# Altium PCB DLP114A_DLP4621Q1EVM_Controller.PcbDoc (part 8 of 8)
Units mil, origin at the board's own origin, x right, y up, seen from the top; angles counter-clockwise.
Board outline 4803.15 x 2598.43 mil, 14 copper layers (Top Layer, GND 1, SIGNAL 1, GND 2, SIGNAL 2, PWR SPLIT PLANE 1, GND 3, GND 4, PWR SPLIT PLANE 2, SIGNAL 3, GND 5, SIGNAL 4, GND 6, Bottom Layer), stack 91.4 mil thick; 489 components, 394 nets, 1925 pads, 1273 vias.
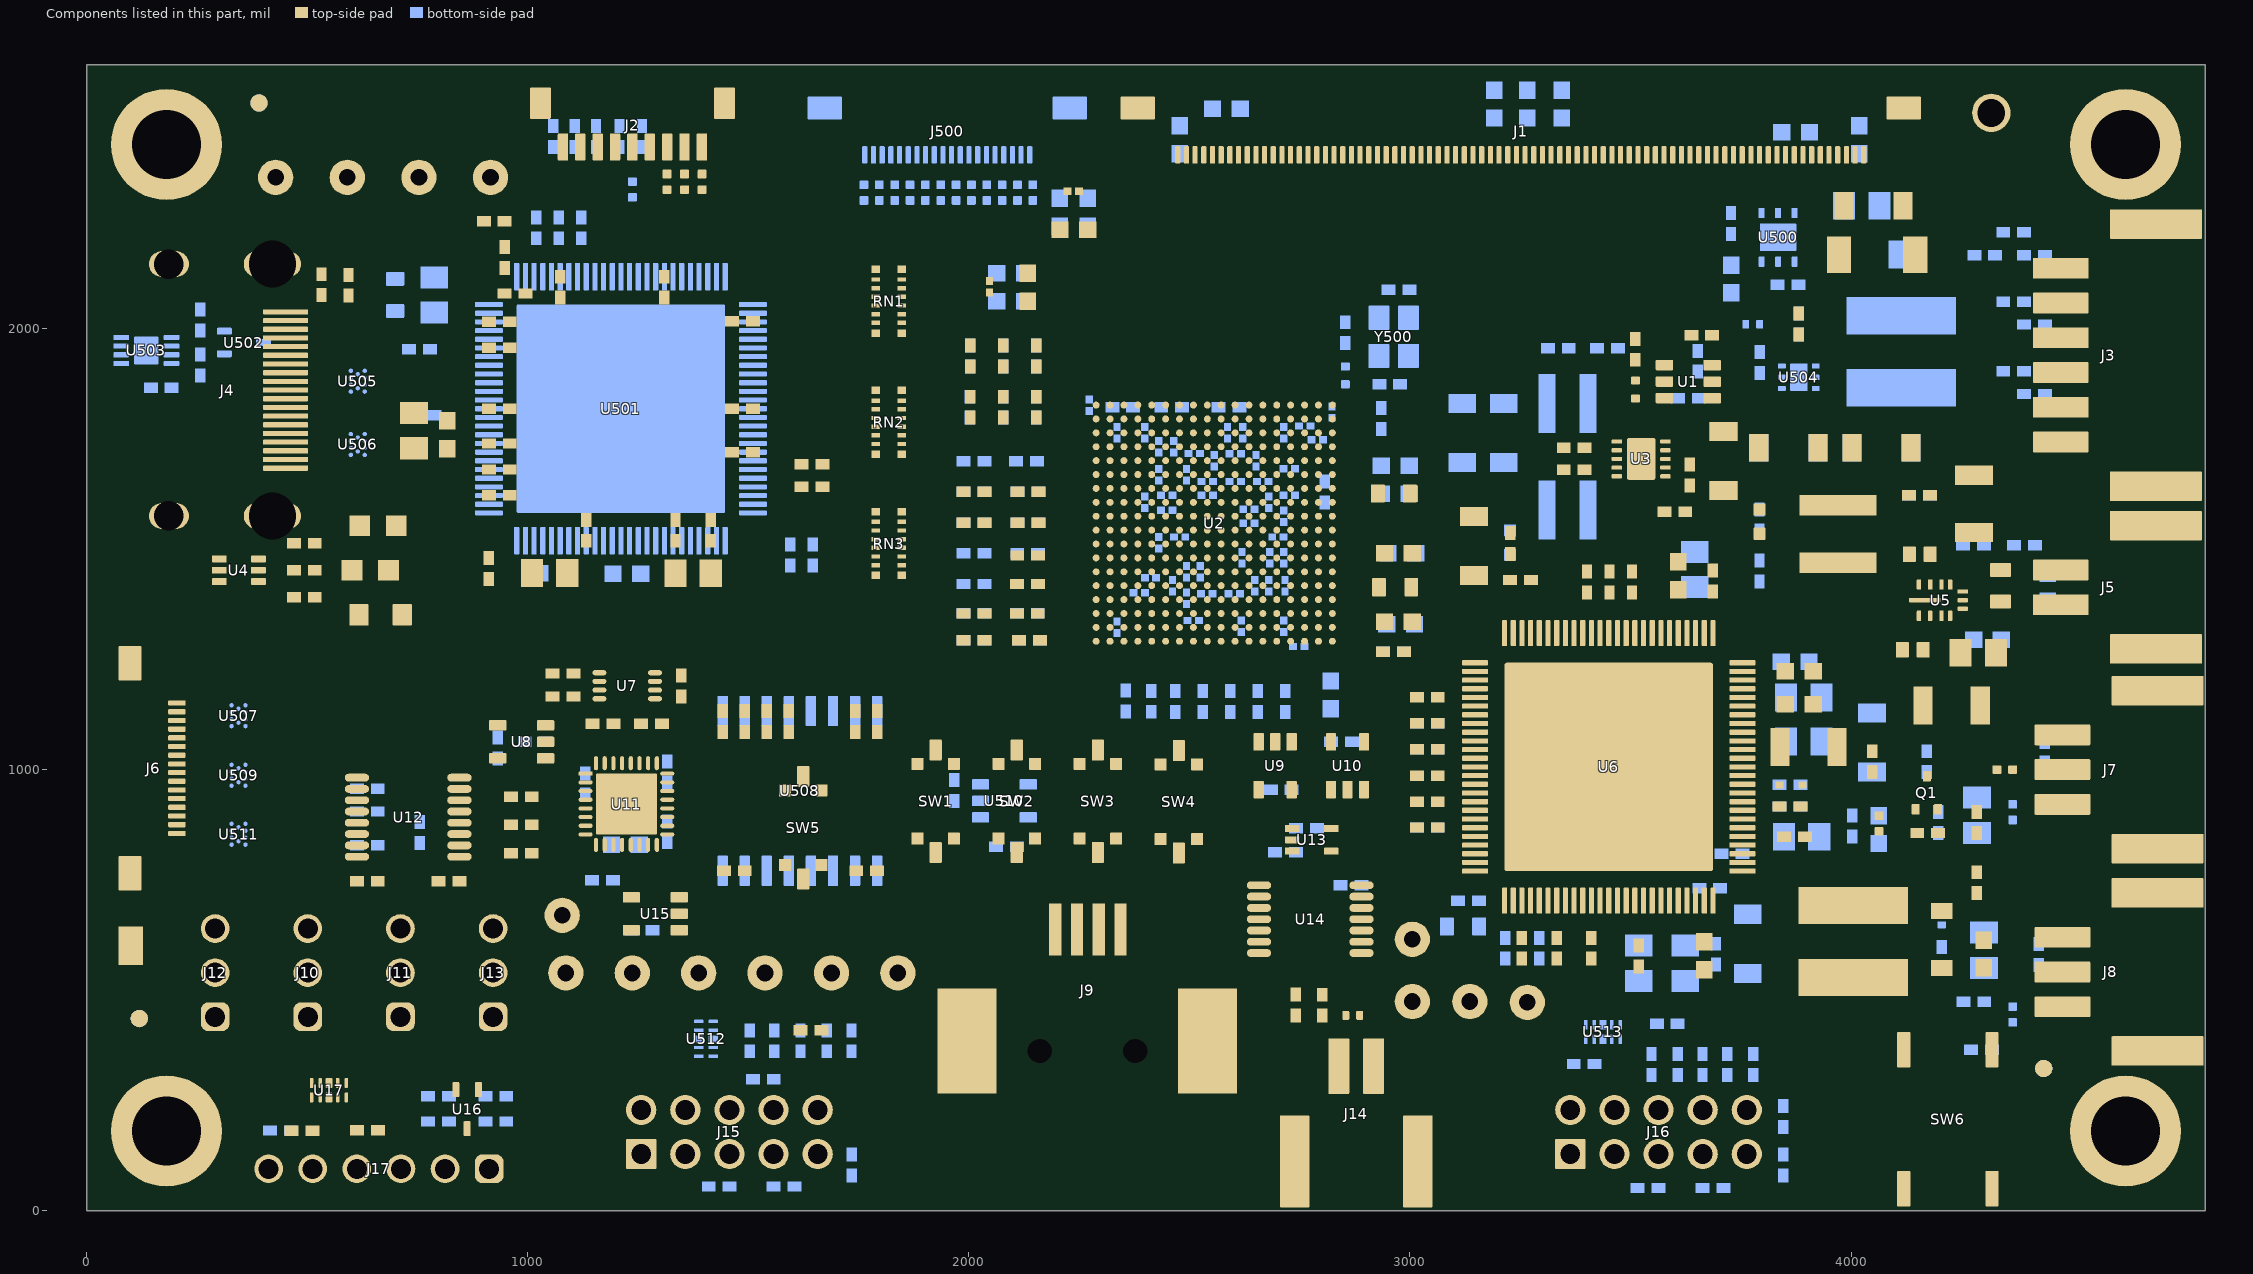
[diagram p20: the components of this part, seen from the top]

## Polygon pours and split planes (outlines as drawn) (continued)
N8V on Bottom Layer "NONET_L-01_P-001" (solid, remove dead copper, pour order 314): 4214.83,1016.03 4260.35,1061.55 4339.43,1061.55 4344.49,1056.5 4344.49,1006.94 4340.09,1002.55 4274.68,1002.55 4236.22,964.09 4184.99,964.09 4163.57,942.67 4013.97,942.67 4009.82,946.83 4009.82,1014.24 4011.61,1016.03
DMD_VRST on Bottom Layer "NONET_L-01_P-001" (solid, remove dead copper, pour order 309): 3244.86,2498.12 3287.33,2498.12 3290.74,2494.71 3290.74,2428.89 3286.34,2424.48 3243.62,2424.48 3239.9,2428.21 3239.9,2496.57 3241.46,2498.14
DMD_VOFS on Bottom Layer "NONET_L-01_P-001" (solid, remove dead copper, pour order 312): 2530.65,2459.41 2530.65,2517.24 2532.86,2519.46 2572.48,2519.46 2574.26,2517.67 2574.26,2430.32 2570.79,2427.3 2570.77,2427.28 2543.45,2427.28 2540.79,2429.94 2540.79,2449.26
DMD_VOFS on Bottom Layer "NONET_L-01_P-001" (solid, remove dead copper, pour order 311): 3323.6,2498.12 3373.61,2498.12 3384.83,2486.9 3384.83,2431.84 3377.47,2424.48 3336.05,2424.48 3318.64,2441.89 3318.64,2496.57 3320.21,2498.14
DMD_VOFS on Bottom Layer "NONET_L-01_P-001" (solid, remove dead copper, pour order 310): 3884.99,2427.07 3884.99,2467.09 3900.29,2482.39 3955.53,2482.39 3961.9,2476.02 3961.9,2433.63 3952.86,2424.59 3887.46,2424.59
DMD_VBIAS on Bottom Layer "NONET_L-01_P-001" (solid, remove dead copper, pour order 308): 3195.36,2498.12 3214.29,2498.12 3225.25,2487.17 3225.25,2430.45 3219.28,2424.48 3178.49,2424.48 3171.65,2431.32 3171.65,2496.51 3173.37,2498.23
P1P8V on Bottom Layer "BOTTOM_LAYER_P1P8V_P207" (solid, pour order 207): 3331.8,1965.29 3331.8,1716.49 3326.37,1711.07 3267.29,1711.07 3261.34,1717.02 3261.34,1766.61 3253.43,1774.52 3092.07,1774.52 3083.79,1782.39 3083.79,1957.65 3095.73,1969.6 3327.49,1969.6
V_DVI_DVDD on Bottom Layer "BOTTOM_LAYER_V_DVI_DVDD_P257" (solid, remove dead copper, pour order 257): 1068.6,1464.8 1068.6,1418.82 1074.85,1412.57 1143.39,1412.57 1148.39,1417.56 1148.39,1465 1141.97,1471.42 1075.22,1471.42
V_DVI_OVDD on Bottom Layer "BOTTOM_LAYER_V_DVI_OVDD_P256" (solid, remove dead copper, pour order 256): 1238.24,1472.71 1339.45,1472.71 1344.59,1467.58 1344.59,1416.59 1338.98,1410.99 1241.35,1410.99 1235.46,1416.87 1235.46,1469.93
V_DVI_PVDD on Bottom Layer "BOTTOM_LAYER_V_DVI_PVDD_P250" (solid, remove dead copper, pour order 250): 670.86,2065.32 826.27,2065.32 831.4,2060.2 831.4,2003.55 825.76,1997.91 755.91,1997.91 746.38,1988.38 672.33,1988.38 666.11,1994.6 666.11,2060.57
P6P5V on Bottom Layer "NONET_L-01_P-001" (solid, remove dead copper, pour order 190): 3875.71,1028.11 3703.11,1028.11 3693.55,1037.68 3693.55,1096.86 3701.83,1105.14 3787.07,1105.14 3817.69,1135.76 3817.69,1192.82 3821.64,1196.77 3878.7,1196.77 3882.02,1193.45 3882.02,1034.43
NetC48_1 on Bottom Layer "NONET_L-01_P-001" (solid, remove dead copper, pour order 183): 3806.65,968.55 3783.26,968.55 3780.36,965.65 3780.36,901.79 3785.39,896.76 3850.69,896.76 3854.75,900.83 3854.75,977.4 3852.33,979.81 3817.92,979.81
VIN_MAIN on Bottom Layer "NONET_L-01_P-001" (solid, remove dead copper, pour order 189): 4148.24,1577.33 4148.24,1517.48 4134.38,1503.62 4134.38,1441.93 4148.24,1428.44 4148.24,1335.77 4109.64,1297.17 4109.64,1081.31 4118.89,1072.06 4217.22,1072.06 4226.35,1081.19 4226.35,1431.99 4201.51,1456.83 4201.51,1473.6 4216.14,1488.23 4262.08,1488.23 4270.41,1496.56 4270.41,1577.15 4262.53,1585.03 4155.94,1585.03
VIN on Bottom Layer "BOTTOM_LAYER_VIN_P188" (solid, pour order 188): 4464.53,1401.69 4329.89,1401.69 4325.37,1397.18 4325.37,1333.12 4330.21,1328.28 4464.74,1328.28 4469.41,1332.96 4469.41,1396.81
P3P3V on Bottom Layer "BOTTOM_LAYER_P3P3V_P222" (solid, remove dead copper, pour order 222): 751.12,2167.83 751.12,2092.76 755.5,2088.38 819.11,2088.38 823.67,2092.93 823.67,2167.85 818.32,2173.2 756.5,2173.2
DVI_5V on Bottom Layer "BOTTOM_LAYER_DVI_5V_P221" (solid, remove dead copper, pour order 221): 172.34,1923.14 172.34,1845.65 180.13,1837.85 266.83,1837.85 272.33,1843.35 272.33,1910.14 267.98,1914.48 236.83,1914.48 224.71,1926.6 175.8,1926.6
GND on Bottom Layer "BOTTOM_LAYER_GND_P220" (solid, remove dead copper, pour order 220): 159.26,1829.96 42.6,1829.96 20.79,1851.77 20.79,1995.36 39.89,2014.46 154.18,2014.46 164.07,2004.57 164.07,1834.77
P6P5V on Bottom Layer "BOTTOM_LAYER_P6P5V_P210" (solid, remove dead copper, pour order 210): 3465.25,628.92 3549.16,628.92 3551.14,626.94 3551.14,575.15 3549.55,573.57 3465.53,573.57 3461.42,577.68 3461.42,625.09
P1P1V on Bottom Layer "BOTTOM_LAYER_P1P1V_P208" (solid, remove dead copper, pour order 208): 3337.5,1658.56 3273.06,1658.56 3245.06,1630.56 3108.77,1630.56 3102.7,1624.5 3102.7,1523.1 3109.02,1516.78 3335.44,1516.78 3341.28,1522.62 3341.28,1654.77
NetL520_1 on Bottom Layer "BOTTOM_LAYER_NETL520_1_P206" (solid, pour order 206): 3383.23,1515.51 3376.17,1522.56 3376.17,1666.45 3382.91,1673.18 3475.23,1673.18 3481.63,1666.79 3481.63,1523.59 3473.55,1515.51
NetL518_1 on Bottom Layer "BOTTOM_LAYER_NETL518_1_P205" (solid, pour order 205): 3380.14,1897.92 3376.17,1893.95 3376.17,1742.54 3382.36,1736.34 3475.77,1736.34 3481.63,1742.2 3481.63,1893.58 3477.28,1897.92
P3P3V on Bottom Layer "NONET_L-01_P-001" (solid, remove dead copper, pour order 186): 3620.57,1799.12 3527.17,1799.12 3523.75,1802.55 3523.75,1849.53 3531.19,1856.97 3621.49,1856.97 3623.36,1855.11 3623.36,1801.91
GND on Bottom Layer "BOTTOM_LAYER_GND_P200" (solid, remove dead copper, pour order 200): 3768.5,1763.14 3812.87,1763.14 3815.15,1760.86 3815.15,1695.71 3812.63,1693.18 3746.96,1693.18 3705.66,1734.48 3652.14,1734.48 3647.06,1739.57 3647.06,1789.36 3652.02,1794.32 3737.32,1794.32
GND on Bottom Layer "BOTTOM_LAYER_GND_P198" (solid, remove dead copper, pour order 198): 4036.96,2323.59 4036.96,2139.63 4045.17,2131.41 4182.59,2131.41 4188.82,2137.65 4188.82,2322.16 4179.16,2331.83 4045.19,2331.83
P6P5V on Bottom Layer "NONET_L-01_P-001" (solid, remove dead copper, pour order 194): 3918.46,2059.86 3918.46,2022.25 3913.1,2016.89 3863.52,2016.89 3859.21,2021.2 3859.21,2158.7 3865.72,2165.21 3886.46,2165.21 3891.71,2170.46 3891.71,2235.48 3879.93,2247.25 3865.21,2247.25 3858.75,2253.72 3858.75,2309.46 3866.8,2317.51 4009.45,2317.51 4016.98,2309.98 4016.98,2107.05 4006.74,2096.13 3954.73,2096.13
P3P3V_REG on Bottom Layer "NONET_L-01_P-001" (solid, remove dead copper, pour order 195): 3638.43,1915.22 3641.72,1918.51 3694.92,1918.51 3699.88,1913.55 3699.88,1869.16 3709.4,1859.63 3781.61,1859.63 3797.43,1843.8 3901.03,1843.8 3911,1853.78 3911,1870.18 3913.37,1872.55 3953.99,1872.55 4004.51,1923.07 4234.68,1923.07 4242.81,1914.93 4242.81,1797.36 4234.91,1789.46 4105.17,1789.46 4074.97,1759.26 4074.97,1596.53 4052.01,1573.57 3679.86,1573.57 3672.28,1581.14 3672.29,1663.65 3680.34,1671.71 3818.5,1671.71 3830.88,1684.09 3830.88,1766.83 3818.25,1779.46 3774.19,1779.46 3744.2,1809.45 3646.55,1809.45 3638.43,1817.57
P1P8V on Bottom Layer "NONET_L-01_P-001" (solid, remove dead copper, pour order 182): 4001.35,2369.61 4059.83,2369.61 4064.84,2374.62 4064.84,2417.43 4059.52,2422.75 4000.95,2422.75 3998.49,2420.44 3998.49,2372.47
NetD1_2 on Bottom Layer "NONET_L-01_P-001" (solid, remove dead copper, pour order 193): 3941.96,1907.78 3914.36,1907.78 3911.49,1910.66 3911.49,1988.57 3934.54,2011.63 3934.54,2052.29 3963.23,2080.99 4030.69,2080.99 4052.06,2102.36 4235.54,2102.36 4245.76,2092.13 4245.76,1982.38 4238.89,1975.51 4009.69,1975.51
NetC26_1 on Bottom Layer "NONET_L-01_P-001" (solid, remove dead copper, pour order 181): 3775.99,1455.89 3804.92,1455.89 3807.57,1458.55 3807.57,1555.56 3804.68,1558.45 3779.16,1558.45 3775.12,1554.42 3775.12,1456.76
NetR500_1 on Bottom Layer "NONET_L-01_P-001" (solid, remove dead copper, pour order 187): 3843.62,2250.7 3843.62,2298.1 3838.99,2302.73 3712.19,2302.73 3708.47,2299 3708.47,2251.28 3714.03,2245.71 3774.73,2245.71 3777.43,2248.4 3841.32,2248.4
P3P3V_TPS99K on Bottom Layer "NONET_L-01_P-001" (solid, remove dead copper, pour order 192): 3637.54,2230.75 3746.59,2230.75 3751,2226.34 3751,2124.05 3747.92,2120.97 3695.97,2120.97 3687.96,2112.96 3687.96,1938.39 3683.44,1933.87 3625.56,1933.87 3622.23,1937.21 3622.23,2215.43
PMIC_ADC_VREF on Bottom Layer "NONET_L-01_P-001" (solid, remove dead copper, pour order 191): 4308.09,1887.98 4359.1,1887.98 4361.23,1890.11 4361.23,2229.77 4359.24,2231.76 4309.14,2231.76 4305.5,2228.12 4305.5,1890.57
P6P5V on PWR SPLIT PLANE 1 "PWR_SPLIT_PLANE_1_P6P5V_P280" (solid, remove dead copper, pour order 280): 1184.59,2238.32 1569.16,2238.32 1635.99,2171.49 2894.19,2171.49 2961.51,2238.81 3095.29,2374.63 3486.95,2374.63 3567.35,2294.23 3567.35,2104.16 3586.41,2085.1 4073.69,2085.1 4139.7,2151.12 4139.7,2460.23 4036.58,2563.35 1198.96,2563.35 1167.18,2531.56 1167.18,2255.74
P3P3V on PWR SPLIT PLANE 1 "PWR_SPLIT_PLANE_1_P3P3V_P283" (solid, remove dead copper, pour order 283): 3499.27,2328.41 3254.09,2328.41 3219.49,2363.01 3109.65,2363.01 2894.99,2148.36 1728.92,2148.36 1678.65,2098.09 1678.65,1587.6 1569.26,1480.72 1430.96,1480.72 1349.56,1399.31 1247.89,1399.31 1171.77,1475.43 878.18,1475.43 786.6,1567.01 786.6,2006.36 1008.59,2228.35 1121.46,2228.35 1147.51,2254.4 1147.51,2546.21 1095.3,2598.43 0,2598.43 0,35.85 2823.11,35.85 3024.59,237.34 3024.05,687.82 3024.05,1105.05 3024.83,1105.83 3024.83,1209.87 3127.98,1313.02 3527.81,1313.02 3633.61,1418.82 3633.61,1862.56 3548.81,1947.36 3548.81,2278.88
VCC18A_LVDS on PWR SPLIT PLANE 1 "PWR_SPLIT_PLANE_1_VCC18A_LVDS_P279" (solid, remove dead copper, pour order 279): 2833.17,1628.58 2833.17,1679.19 2804.02,1709.69 2689.43,1709.69 2657.56,1675.23 2231.79,1675.23 2226.82,1680.2 2226.82,1847.12 2241.53,1860.48 2910.37,1860.48 2937.16,1833.68 2937.16,1627.64 2921.67,1612.14 2849.61,1612.14
P3P3V_TPS99K on PWR SPLIT PLANE 1 "PWR_SPLIT_PLANE_1_P3P3V_TPS99K_P282" (solid, remove dead copper, pour order 282): 3576.68,2070.19 3565.21,2058.71 3565.21,1952.02 3648.27,1868.95 3648.27,1402.67 3542.8,1297.2 3134.26,1297.2 3039.54,1202.48 3039.54,105.64 3112.91,32.27 4193.96,32.27 4328.66,162.87 4328.66,2001.9 4260.37,2070.19
V_DVI_OVDD on PWR SPLIT PLANE 1 "PWR_SPLIT_PLANE_1_V_DVI_OVDD_P281" (solid, remove dead copper, pour order 281): 1423.44,1643.81 1439.51,1665.39 1439.51,2033.6 1426.62,2046.49 1310.47,2046.49 1299.12,2057.85 1299.12,2189.51 1309.12,2198.44 1580.02,2198.44 1648.42,2130.05 1648.42,1585.58 1562.08,1496.27 1430.01,1496.27 1344.73,1410.99 1257.87,1410.99 1178.29,1490.57 885.6,1490.57 834.27,1541.9 834.27,1620.62 857.46,1643.81
P1P8V on PWR SPLIT PLANE 2 "PWR_SPLIT_PLANE_2_P1P8V_P290" (solid, remove dead copper, pour order 290): 3258.18,1301.58 3258.18,1255.07 3260.65,1252.6 3286.81,1252.6 3288.78,1254.57 3288.78,1274.92 3302.86,1289 3578.44,1289 3697.54,1408.1 3697.54,1588.93 3651.23,1635.25 3651.23,1924.11 3695.33,1968.21 4048.78,1968.21 4129.03,2048.46 4129.03,2466.03 4030.32,2564.73 2469.66,2564.73 2380.33,2475.41 2380.33,1704.85 2387.27,1697.92 2798.73,1697.92 2845.17,1651.48 2898.33,1651.48 2936.02,1613.79 3063.83,1613.79 3095.9,1645.85 3296.08,1645.85 3320.93,1621 3320.93,1452.7 3395,1378.63 3395,1342.04 3382.9,1329.93 3286.53,1329.93
P1P1V on PWR SPLIT PLANE 2 "PWR_SPLIT_PLANE_2_P1P1V_P284" (solid, remove dead copper, pour order 284): 2186.35,2210.25 2186.35,2372.76 2195.45,2381.87 2352.13,2381.87 2365.11,2368.89 2365.11,1808.13 2354.24,1797.26 2354.24,1679.13 2361.72,1671.65 2802.53,1671.65 2876.59,1597.59 3069.97,1597.59 3103.19,1630.81 3289.71,1630.81 3304.43,1616.09 3304.43,1467.91 3269.09,1432.57 3269.09,1333.32 3252.51,1317.22 2039.18,1317.22 1977.61,1378.79 1977.61,2180.11 1997.12,2199.65 2175.74,2199.65
P6P5V on PWR SPLIT PLANE 2 "PWR_SPLIT_PLANE_2_P6P5V_P292" (solid, remove dead copper, pour order 292): 1110.26,2054.32 1128.88,2035.7 1128.88,1651.33 1146.73,1633.48 1322.26,1633.48 1333.67,1622.06 1333.67,1590.41 1364.89,1559.2 1364.89,1158.95 1946.83,577 2482.46,577 3616.72,577 3770.33,577 3873.44,680.12 3873.44,1240.62 3832.75,1281.31 3778.42,1281.31 3758.12,1301.61 3614.28,1301.61 3607.59,1294.92 3607.59,1257.14 3576.91,1226.47 3576.91,1210.61 3565.28,1198.98 3230.06,1198.98 3218.12,1210.28 3218.12,1251.48 3176.88,1292.72 3067.54,1292.72 2021.1,1292.72 1957.08,1356.74 1957.08,2220.01 1935.59,2241.5 1754.05,2241.5 1653.55,2342 1158.82,2342 1146.54,2329.72 1146.54,2277.33 1110.26,2241.05
P3P3V_REG on PWR SPLIT PLANE 2 "PWR_SPLIT_PLANE_2_P3P3V_REG_P286" (solid, remove dead copper, pour order 286): 515.32,1577.02 1299.2,1577.02 1333.56,1542.67 1333.56,1155.11 1934.07,554.6 3784.34,554.6 3900.2,670.45 3900.2,1221.29 3963.12,1284.22 4287.7,1284.22 4341.29,1343.02 4341.29,1533.05 4297.32,1577.02 3743.32,1577.02 3681.14,1639.2 3681.14,1912.02 3718.49,1949.38 4709.01,1949.38 4803.15,1855.24 4803.15,0 515.99,0 415.74,100.25 415.74,1477.44
V_DVI_AVDD on PWR SPLIT PLANE 2 "PWR_SPLIT_PLANE_2_V_DVI_AVDD_P285" (solid, remove dead copper, pour order 285): 767.04,1702.67 782.74,1686.97 962.76,1686.97 980.3,1704.51 980.3,1958.27 966.1,1972.47 782.41,1972.47 767.04,1957.09
NetC26_1 on PWR SPLIT PLANE 2 "PWR_SPLIT_PLANE_2_NETC26_1_P291" (solid, remove dead copper, pour order 291): 3796.21,1561.87 3765.98,1531.64 3766.14,1331.76 3795.1,1302.8 4278.13,1302.8 4323.22,1347.89 4323.22,1524.22 4285.57,1561.87
DMD_VRST on SIGNAL 4 "NONET_L-01_P-001" (solid, remove dead copper, pour order 337): 3696.85,769.72 3696.81,635.02 3824.27,507.56 4239.02,507.56 4278.43,546.96 4278.43,722.39 4252.13,748.69 3850.88,748.69 3812.29,787.28 3714.41,787.28
CY_VBUS on SIGNAL 4 "SIGNAL_4_CY_VBUS_P287" (solid, remove dead copper, pour order 287): 2432.18,531.95 2432.18,801.85 2412.33,821.7 2215.82,821.7 2163.62,769.51 2015.23,769.51 1815.58,969.15 1410.64,969.15 1323.66,882.17 1323.66,808.26 1327.44,804.48 1327.44,616.17 1354.15,589.47 1864.54,589.47 1952.97,501.04 2401.27,501.04
N8V_FIL on SIGNAL 4 "NONET_L-01_P-001" (solid, remove dead copper, pour order 322): 4362.05,1031.03 4354.33,1023.31 4354.33,1001.95 4328.81,976.43 4328.81,516.5 4343.55,501.76 4462.61,501.76 4479.11,518.26 4479.11,1020.13 4468.2,1031.03
VIN_MAIN on SIGNAL 4 "SIGNAL_4_VIN_MAIN_P307" (solid, remove dead copper, pour order 307): 3852.33,854.37 3876.82,829.88 4233.08,829.88 4254.79,851.59 4254.79,1125.35 4228.66,1151.48 3872.32,1151.48 3852.33,1131.49
DMD_VBIAS on SIGNAL 1 "NONET_L-01_P-001" (solid, remove dead copper, pour order 333): 3699.97,681.49 3699.97,722.39 3738.28,760.7 3738.28,812.76 3757.93,832.61 3989.87,832.61 4093.68,936.41 4093.68,995.77 3916.97,1172.48 3916.97,1737.63 3356.23,2298.38 3199.21,2298.38 3168.25,2329.34 3168.25,2442.87 3201.26,2475.88 3514.61,2475.88 4142.25,1848.23 4142.25,1229.03 4252.81,1118.48 4252.81,845.37 4077.96,670.52 3710.68,670.79
DMD_VOFS on SIGNAL 1 "NONET_L-01_P-001" (solid, remove dead copper, pour order 332): 3573.44,624.38 3559.94,610.87 3559.94,494.96 3594.41,460.48 4210.76,460.48 4477.52,727.25 4477.52,2220.9 4200,2498.42 3954.34,2498.42 3935.97,2480.05 3935.97,2330.77 4295.53,1971.22 4295.53,823.42 4096.49,624.38
N8V on SIGNAL 1 "NONET_L-01_P-001" (solid, remove dead copper, pour order 326): 3717.76,1026.54 3698.96,1026.54 3694.86,1022.43 3694.86,990.66 3699.57,985.95 3765.76,985.95 3800.2,1020.4 3923.62,1020.4 4010.68,933.33 4052.15,933.33 4061.6,942.78 4061.6,982.68 4054.29,989.99 4036.63,989.99 3946.86,1079.76 3770.98,1079.76
P1P8V on SIGNAL 1 "NONET_L-01_P-001" (solid, remove dead copper, pour order 323): 3079.48,1837.7 3079.48,1690.27 3023.83,1634.61 3023.83,1596.67 3079.48,1541.02 3079.48,1309.98 3100,1289.47 3246.88,1289.47 3258.56,1277.78 3258.56,1249.3 3261.28,1246.58 3285.44,1246.58 3288.42,1249.55 3288.42,1279.64 3298.25,1289.47 3663.41,1289.47 3697.55,1323.6 3697.55,1843.41 3665.68,1875.28 3117.06,1875.28
GND on GND 1 "GND_1_GND_P216" (solid, remove dead copper, pour order 216): 0,2598.43 0,0 4803.15,0 4803.15,2598.43
GND on GND 6 "GND_6_GND_P247" (solid, remove dead copper, pour order 247): 0,2598.43 0,0 4803.15,0 4803.15,2598.43
GND on GND 5 "GND_5_GND_P261" (solid, remove dead copper, pour order 261): 0,2598.43 0,0 4803.15,0 4803.15,2598.43
GND on GND 2 "GND_2_GND_P262" (solid, remove dead copper, pour order 262): 0,2598.43 0,0 4803.15,0 4803.15,2598.43
GND on GND 3 "GND_3_GND_P324" (solid, remove dead copper, pour order 324): 0,2598.43 0,0 4803.15,0 4803.15,2598.43
GND on GND 4 "GND_4_GND_P325" (solid, remove dead copper, pour order 325): 0,2598.43 0,0 4803.15,0 4803.15,2598.43

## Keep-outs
Keep-Out Layer:
  the board outline again, w50
  text ".Layer_Name" at 577,-858.49 h60

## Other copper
Top Layer:
  region net DMD_VOFS: 3673.18,733.32 3662.48,733.39 3660.6,731.52 3660.6,649.42 3637.26,626.07 3575.87,626.07 3564.71,614.91 3564.71,582.47 3572.57,574.61 3612.7,574.61 3627.24,589.15 3686.65,589.15 3689.45,591.95 3689.45,640.44 3673.76,656.13 3673.76,732.74
  region net DMD_VOFS: 2557.83,2373.45 2546.89,2373.34 2544.66,2375.57 2544.66,2430.24 2541.49,2433.41 2541.49,2475.14 2545.84,2479.49 2558.3,2479.49 2563.47,2474.32 2563.47,2432.94 2559.47,2428.94 2559.47,2375.09
  region net DMD_VOFS: 3293.74,2375.46 3293.75,2417.37 3326.77,2450.39 3380.26,2450.39 3384.9,2445.75 3384.9,2433.2 3379.03,2427.33 3319.11,2427.33 3306.44,2414.65 3306.44,2375 3304.98,2373.54 3294.92,2373.54 3293.74,2374.72
  region net DMD_VRST: 3279.28,2447.85 3284.76,2447.85 3290.37,2442.24 3290.37,2425.98 3287.04,2422.81 3287.04,2374.99 3285.73,2373.68 3275.27,2373.68 3274.06,2374.89 3274.06,2376.63 3274.06,2416.47 3265.14,2425.39 3245.27,2425.39 3238.72,2431.94 3238.72,2440.86 3245.75,2447.89 3279.24,2447.89
  region net DMD_VBIAS: 3215,2416.47 3206.09,2425.39 3181.18,2425.39 3174.85,2431.71 3174.85,2441.08 3181.66,2447.89 3220.19,2447.89 3227.99,2440.08 3227.99,2374.99 3226.68,2373.68 3216.21,2373.68 3215,2374.89 3215,2376.63
  region net DMD_VOFS: 3938.83,2476.88 3944.75,2482.8 3956.88,2482.8 3961.57,2478.1 3961.57,2431.13 3956.32,2425.74 3956.02,2374.68 3955.02,2373.68 3944.56,2373.68 3943.35,2374.89 3943.35,2376.63 3943.35,2425.69 3938.83,2430.2
  text ".Layer_Name" at 577,-858.49 h60
Bottom Layer:
  text ".Layer_Name" at 577,-858.49 h60

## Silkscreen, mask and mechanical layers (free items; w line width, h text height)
Top Overlay:
  circle w10: c222.02,1168.9 r0.77
  circle w10: c2375.79,686.59 r5.17
  circle w10: c2799.86,384.08 r4.38
  circle w10: c3594.49,1652.46 r0.39
  circle w10: c269.73,1480.89 r0.39
  circle w10: c4139.27,1324.86 r0.39
  circle w10: c3114.67,1264.52 r0.39
  circle w10: c1303.9,1145.61 r0.39
  circle w10: c1076.29,1022.62 r0.39
  circle w10: c2740.28,1097.24 r0.39
  circle w10: c2803.84,926.7 r0.39
  circle w10: c884.16,797.12 r0.39
  circle w10: c2704.49,884.11 r0.39
  circle w10: c2619.45,748.81 r0.39
  circle w10: c1370.35,616.45 r0.39
  circle w10: c503.49,233.22 r0.39
  lines w6: 802.46,1197.2 819.66,1180 819.66,1066.29 926.15,959.79 ; 850.89,1976.38 877.77,1976.38 ; 866.77,2020.83 878.53,2020.83 ; 887.63,1846.92 887.56,1846.92 887.56,1902.62 897.32,1912.38 ; 999.24,1686.3 1021.84,1686.3 1032.84,1675.3 1032.84,1612.47 ; 1002.18,1153.57 1025.67,1130.09 1085.96,1130.09 1103.92,1112.12 ; 1012.41,1196.74 1022.13,1187.03 ; 1027.95,2075.19 1033.35,2080.58 1033.35,2104.54 ; 1180.73,588.26 1195.77,588.26 1205.3,578.73 ; 1376.81,455.29 1385.49,463.97 1385.49,485.75 ; 2094.93,1261 2094.93,1143.26 2121.23,1116.96 ; 2198.59,1569.1 2205.2,1575.71 2205.2,1686.91 ; 2238.17,1921.52 2355.79,1921.52 2379.3,1945.04 ; 2937.43,1669.38 2937.43,1887.51 2972.66,1922.74 2998.57,1922.74 ; 3072.53,1194.65 3072.53,1647.08 3125.66,1700.21 3125.66,1947.71 3147.2,1969.25 ; 3148.01,411.55 3163.64,411.55 3203.65,451.56 3220.66,451.56 ; 3733.28,1798.61 3748.72,1814.05 ; 4182.46,1659.79 4182.46,1677.34 4197.08,1691.96
  lines w6.1: 517.51,1260.34 534.74,1277.57 534.74,1356.83 ; 2184.2,1971.25 2258.95,2045.99 2315.01,2045.99 2325.6,2056.58 ; 2186.2,1869.55 2238.17,1921.52 ; 3831.1,1263.53 3831.1,1321.79 3840.06,1330.75 ; 4000.96,1078.95 4009.07,1087.06 4009.07,1112.32
  text "HL Driver I/F" at 1473.96,2410.62 h30
  text "PCLK" at 929.89,2404.44 h30 r90
  text "DATAEN" at 806.59,2401.58 h30 r90
  text "DMD I/F" at 2149.66,2394.15 h30
  text "DLP4620SQ1EVM / DLP4621Q1EVM" at 1478.6,2308.87 h30
  text "LED Therm" at 4228.76,2270.15 h30
  text "HSYNC" at 350.71,2258.61 h30
  text "VSYNC" at 528.21,2258.61 h30
  text "DLP090 / DLP092" at 1645.38,2244.5 h30
  text "HDMI" at 225.97,2175.39 h30
  text "Input Power" at 4408.42,1470.54 h45 r90
  text "OpenLDI" at 12.97,1312.95 h30
  text "PhotoDiode1" at 4402.85,1028.29 h45 r90
  text "USB" at 2293.87,669.64 h30
  text "DMUX0" at 2938.22,669.83 h30
  text "AMUX1" at 3170.91,528.1 h30 r90
  text "TESTPT3" at 1931.32,524.05 h30 r90
  text "TESTPT0" at 1172.97,496.75 h30 r90
  text "TESTPT1" at 1627.48,481.07 h30 r90
  text "TESTPT2" at 1783.39,481.07 h30 r90
  text "HOST_SPI_MODE" at 987.84,440.97 h30
  text "DMUX1" at 2960.55,391.95 h30
  text "PMIC SPI" at 3540.87,376.78 h30
  text "Host SPI" at 1317.95,370.53 h30
  text "PhotoDiode2" at 4396.61,371.07 h30 r90
  text "Host SPI CLK" at 430.5,362.29 h30 r90
  text "Host SPI CSZ" at 223.09,360.25 h30 r90
  text "Host SPI POCI" at 854.69,345.45 h30 r90
  text "Host SPI PICO" at 636.57,332.93 h30 r90
  text "AMUX0" at 3137.41,284.2 h30 r90
  text "Proj_ON" at 4422.19,35.94 h30 r90
  text "Host I2C" at 1022.48,9.97 h30 r90
  text "FAN PWM" at 2689.63,-142.49 h30 r90
  text ".Layer_Name" at 577,-858.49 h30
Bottom Overlay:
  drawing of 174 lines, arcs and shapes, not listed
  text "TP2" at 632.46,2403.82 h30
  text "DATAEN" at 736.06,2403.11 h30 r270
  text "TP1" at 460.72,2402.39 h30
  text "HUD Driver I/F" at 1570.79,2333.16 h45 r270
  text "TP4" at 826.71,2305.22 h30 r270
  text "A" at 3520.71,2299.7 h30
  text "HSYNC" at 490.67,2258.61 h30
  text "VSYNC" at 666.25,2257.99 h30
  text "TP3" at 797.76,2254.26 h30
  text "PCLK" at 964.17,2253.89 h30
  text "A" at 2724.07,1820.46 h30
  text "B" at 2424.18,1268.45 h30
  text "TP5" at 993.69,631.34 h30 r270
  text "TP10" at 1590.84,595.02 h30
  text "TP12" at 1886.34,593.82 h30
  text "TP11" at 1734.99,592.62 h30
  text "TP6" at 3052.53,534.31 h30
  text "TP8" at 1293.43,499.51 h30 r270
  text "TP9" at 1440.08,499.7 h30 r270
  text "TP7" at 1123.83,455.32 h30
  text "TP13" at 3048.07,388.05 h30
  text "TP14" at 3189.69,388.05 h30
  text "TP15" at 3321.76,388.05 h30
  text "B" at 2176.99,65.9 h30
  text ".Layer_Name" at 577,-858.49 h60
Top Paste:
  text ".Layer_Name" at 577,-858.49 h60
Bottom Paste:
  text ".Layer_Name" at 577,-858.49 h60
Top Solder:
  text ".Layer_Name" at 577,-858.49 h60
  text ".Layer_Name" at 577,-858.49 h60
Bottom Solder:
  text ".Layer_Name" at 577,-858.49 h60
Drill Guide:
  text ".Layer_Name" at 577,-858.49 h60
M1 Board Outline:
  the board outline again, w10
  text ".Layer_Name" at 577,-858.49 h60
M2 Board Dimensions:
  rectangle: 4953.53,92.93 5078.53,217.93
  rectangle: 5078.53,-32.07 5453.53,92.93
  lines w7: 4953.53,92.93 5953.53,92.93 ; 5078.53,-32.07 5078.53,217.93 ; 5203.53,-32.07 5203.53,217.93 ; 5453.53,-32.07 5453.53,217.93 ; 5703.53,-32.07 5703.53,217.93 ; 4953.53,-32.07 5953.53,-32.07 5953.53,217.93 4953.53,217.93 4953.53,-32.07
  text ".Layer_Name" at 577,-858.49 h60
M3 3D STEP Top:
  text ".Layer_Name" at 577,-858.49 h60
M4 3D STEP Bottom:
  text ".Layer_Name" at 577,-858.49 h60
M5 Assembly Top:
  lines w10: -292,-930.17 6308,-930.17 ; -292,-726.83 6310,-726.83 ; -292,-523.5 -292,-1133.5 3713,-1133.5 6310,-1133.5 6310,-523.5 -291.5,-523.5 -291.5,-1133.5 1284,-1133.5 ; 2173,-1133.5 2173,-523.5 ; 3440,-726.83 3440,-523.5 ; 4280,-726.83 4280,-523.5 ; 4902,-1140 4902,-937.17
  text "COMPONENTS MARKED 'DNP' SHOULD NOT BE POPULATED." at 1153.5,-318.5 h60
  text "ASSEMBLY VARIANT:" at 1153,-434 h60
  text ".VariantName" at 2189,-434 h60
  text "PCB VIEWED FROM TOP SIDE" at -228.5,-655.67 h60
  text "BOARD #:" at 2248,-655.67 h60
  text ".PRJ_Number" at 2793.5,-655.67 h60
  text "REV:" at 3638,-655.67 h60
  text ".PCB_Rev" at 3929.5,-655.67 h60
  text "SVN REV:" at 4476,-655.67 h60
  text ".VersionControl_RevNumber" at 4982,-655.67 h60
  text "TID #:" at 2248,-859 h60
  text ".TID" at 2793.5,-859 h60
  text "PLOT NAME =" at -228.5,-1064.34 h60
  text ".plot_File_Name" at 577,-1064.34 h60
  text "GENERATED    :" at 2250,-1064.34 h60
  text ".Print_Date" at 3119.5,-1064.34 h60
  text ".Print_Time" at 3848.5,-1064.34 h60
  text "TEXAS INSTRUMENTS" at 5113,-1064.34 h60
M6 Assembly Bottom:
  lines w10: -292.5,-727.33 6309.5,-727.33 ; -290.5,-930.67 6309.5,-930.67 ; 1115.5,-1140.5 1115.5,-937.67 ; 1737.5,-727.33 1737.5,-524 ; 2577.5,-727.33 2577.5,-524 ; 3844.5,-1134 3844.5,-524 ; 4733.5,-1134 6309,-1134 6309,-524 -292.5,-524 -292.5,-1134 2304.5,-1134 6309.5,-1134 6309.5,-524
  text "COMPONENTS MARKED 'DNP' SHOULD NOT BE POPULATED." at 6102,-318 h60
  text ".VariantName" at 5058,-434 h60
  text "ASSEMBLY VARIANT:" at 6097,-434 h60
  text ".VersionControl_RevNumber" at 1035.5,-656.17 h60
  text "SVN REV:" at 1541.5,-656.17 h60
  text ".PCB_Rev" at 2088,-656.17 h60
  text "REV:" at 2379.5,-656.17 h60
  text ".PRJ_Number" at 3224,-656.17 h60
  text "BOARD #:" at 3769.5,-656.17 h60
  text "PCB VIEWED FROM BOTTOM SIDE" at 6246,-656.17 h60
  text ".TID" at 3224,-859.5 h60
  text "TID #:" at 3769.5,-859.5 h60
  text "TEXAS INSTRUMENTS" at 904.5,-1064.84 h60
  text ".Print_Time" at 2169,-1064.84 h60
  text ".Print_Date" at 2898,-1064.84 h60
  text "GENERATED    :" at 3767.5,-1064.84 h60
  text ".plot_File_Name" at 5440.5,-1064.84 h60
  text "PLOT NAME =" at 6246,-1064.84 h60
M9 Title Sheet:
  drawing of 61 lines, arcs and shapes, not listed
  text "1" at 739.84,12536.5 h70
  text "2" at 3235.5,12536.5 h70
  text "3" at 5724.84,12536.5 h70
  text "4" at 8231.51,12536.5 h70
  text "5" at 10730.5,12536.5 h70
  text "6" at 13235.5,12536.5 h70
  text "A" at 14373.71,9525.4 h70
  text "A" at -430.84,9478.52 h70
  text "B" at -416.5,6893.5 h70
  text "B" at 14383.5,6893.5 h70
  text "C" at -416.5,4513.5 h70
  text "C" at 14383.5,4513.5 h70
  text "D" at -416.5,2138.5 h70
  text "D" at 14383.5,2138.5 h70
  text "PROJECT TITLE:" at 11343.5,277.5 h45
  text ".PRJ_Title" at 11393.5,144.17 h70
  text "DESIGNED FOR:" at 11343.5,-23.5 h45
  text ".PRJ_Customer" at 11393.5,-163.5 h70
  text "E" at -416.5,-231.5 h70
  text "E" at 14383.5,-231.5 h70
  text "FILE NAME:" at 11343.5,-323.5 h45
  text ".PCB_File_Name_No_Path" at 11393.5,-443.5 h70
  text "Texas Instruments (TI) and/or its licensors do not warrant the accuracy or completeness of this specification" at 6374,-605.34 h45
  text "ENGINEER:" at 11343.5,-613.5 h45
  text "LAYOUT BY:" at 12848.5,-613.5 h45
  text "or any information contained therein. TI and/or its licensors do not warrant that this design will meet" at 6329.01,-718 h45
  text ".PRJ_Engineer" at 11393.5,-768.49 h70
  text ".PCB_Layout" at 12899,-768.49 h70
  text "the specifications, will be suitable for your application or fit for any particular purpose, or will operate in" at 6329.01,-830.67 h45
  text ".Layer_Name" at 577,-858.49 h60
  text "ALTIUM DESIGNER VERSION:" at 12848.5,-923.5 h45
  text "an implementation. TI and/or its licensors do not warrant that the design is production worthy. You should" at 6329.01,-943.33 h45
  text "completely validate and test your design implementation to confirm the system functionality for your application." at 6374,-1056 h45
  text ".print_Scale" at 11393.5,-1056.83 h70
  text ".Application_BuildNumber" at 12899,-1056.83 h70
  text "1" at 739.84,-1263.5 h70
  text "2" at 3235.5,-1263.5 h70
  text "3" at 5724.84,-1263.5 h70
  text "4" at 8231.51,-1263.5 h70
  text "5" at 10730.5,-1263.5 h70
  text "6" at 13235.5,-1263.5 h70
M10 Fab Notes:
  drawing of 219 lines, arcs and shapes, not listed
  text "FAB NOTES :" at -22.41,12208.04 h80
  text "1.  BOARD DIMENSION : 122MM X 66MM." at 141.85,11900.97 h80
  text "2. VENDOR MAY ADJUST SOLDERMASK WHEREVER SOLDERMASK PADS ARE THE SAME SIZE (1:1) AS PER THE MANUFACTURING CAPABILITIES AND" at 138.88,11716.65 h80
  text "ALL OTHER SOLDER MASK PADS SHALL NOT BE MODIFIED, PROVIDED NO ADJACENT COPPER IS EXPOSED AND NO CONFLICT IS PRODUCED WITH ANY STATED \"VIA TENTING/COVERING\" REQUIREMENTS." at 367.79,11541.16 h80
  text "3. ALL VIAS ARE TENTED ON BOTH SIDES UNLESS OTHERWISE SOLDER MASK IS OPENED IN GERBER." at 138.88,11383.7 h80
  text "4. TRACES WITH 6.3MIL TO BE 50 OHMS +/-10% SINGLE ENDED ON TOP LAYER & BOTTOM LAYER (L1 & L14)." at 138.35,11178.73 h80
  text "5. TRACES WITH 4.5MIL TO BE 50 OHMS +/-10% SINGLE ENDED ON SIGNAL1, SIGNAL2, SIGNAL3 & SIGNAL4 LAYERS (L3, L5, L10 & L12)." at 123.35,10938.78 h80
  text "6. TRACES WITH 7MIL AND 14MIL SEPERATION TO BE 90 OHMS +/-10% DIFFERENTIAL ON EXTERNAL LAYER(L1)." at 138.35,10770.27 h80
  text "7. TRACES WITH 5MIL AND 9MIL SEPERATION TO BE 90 OHMS +/-10% DIFFERENTIAL ON INTERNAL LAYER(L3)." at 138.35,10558.64 h80
  text "8. TRACES WITH 5.4MIL AND 11.4MIL SEPERATION TO BE 100 OHMS +/-10% DIFFERENTIAL ON EXTERNAL LAYERS(L1 & L14)." at 138.35,10340.14 h80
  text "9. TRACES WITH 4MIL AND 10MIL SEPERATION TO BE 100 OHMS +/-10% DIFFERENTIAL ON INTERNAL LAYERS(L3 & L12)." at 137.04,10146.36 h80
  text "10. 8.01MIL VIAS NEED TO BE FILLED WITH NON-CONDUCTIVE EPOXY-RESIN AND OVERPLATE WITH COPPER. SURFACE MUST BE FLAT," at 106.28,9936.63 h80
  text "FLATNESS TOLERANCE IS +0.000/-0.001\" ON BOTTOM SIDE ONLY AND +0.000/-0.003\" ON TOP SIDE." at 404,9749.47 h80
  text "MINIMUM ANNULAR RING REQUIREMENT IS WAIVED FOR FILLED VIAS." at 401.75,9567.78 h80
  text "DESIGN INFORMATION" at 12382.02,6356.17 h60
  text "MIN. TRACK WIDTH:" at 11737.46,6224.05 h60
  text "8" at 12833.7,6224.05 h60
  text "MIL" at 12988.46,6224.05 h60
  text "5" at 12833.93,6106.21 h60
  text "MIN. CLEARANCE:" at 11737.46,6099.92 h60
  text "MIL" at 12988.46,6099.92 h60
  text "MIN. VIA PAD SIZE:" at 11737.46,5975.8 h60
  text "24" at 12803.71,5975.8 h60
  text "MIL" at 12988.46,5975.8 h60
  text "0.05mm (2MIL)" at 12432.46,5845.9 h60
  text "MINIMUM ANNULAR RING" at 11408.23,5837.67 h60
  text "EXTERNAL" at 13140.46,5837.67 h60
  text "PER" at 11608.23,5727.55 h60
  text "IPC-D-275 CLASS 2 LEVEL C" at 11828.23,5727.54 h60
  text "MIL, HOLES" at 13316.46,5627.07 h60
  text "+/-" at 12924,5618.48 h60
  text "+/-" at 13778,5618.48 h60
  text "REGISTRATION TOLERANCES:" at 11408.23,5617.42 h60
  text "METAL" at 12608,5617.42 h60
  text "5" at 13184.2,5617.42 h60
  text "3" at 14017.2,5617.42 h60
  text "MIL" at 14133.46,5617.42 h60
  text "HOLE SIZE TOLERANCE (UNLESS OTHERWISE SPECIFIED):" at 11408.23,5519.1 h60
  text "+/-" at 13778,5516.23 h60
  text "3" at 14017.2,5515.17 h60
  text "MIL" at 14133.46,5515.17 h60
  text "MATERIAL:" at 11333.46,5377.52 h60
  text "FR-4 High Tg" at 12319.9,5249 h60
  text "X" at 12175.46,5241.01 h60
  text "FR-408" at 11754.46,5236.49 h60
  text "OTHER" at 13242.46,5236.49 h60
  text "93 MIL +/-10%" at 13653.85,5093.52 h55
  text "62 MIL (1.6mm) +/-10%" at 12074.56,5093.46 h60
  text "X" at 13241.26,5091.77 h60
  text "THICKNESS:" at 11408.23,5085.24 h60
  text "OTHER" at 13359.46,5085.24 h60
  text "TOLERANCE:" at 11408.23,4946.92 h60
  text "X" at 12256.46,4946.92 h60
  text "ANSI IPC-6012 TYPE 3 CLASS 2" at 12434.48,4946.92 h60
  text "OTHER +/-" at 12434.46,4802.73 h60
  text "BOW & TWIST:" at 11408.23,4657.54 h60
  text "X" at 12256.46,4657.54 h60
  text "ANSI IPC-6012 TYPE 3 CLASS 2" at 12434.48,4657.54 h60
  text "OTHER +/-" at 12434.46,4510.85 h60
  text "DRILLING:" at 11333.46,4380.23 h60
  text "NC_DRILL FILES" at 13094.46,4275.04 h60
  text "REFERENCE:" at 11408.23,4271.1 h60
  text "X" at 12065.46,4271.01 h60
  text "AS SHOWN" at 12243.46,4271.1 h60
  text "X" at 12966.46,4271.1 h60
  text "OTHER" at 13392.46,4128.85 h60
  text "PTH COPPER THICKNESS:" at 11407.91,4125.32 h60
  text "X" at 12547.14,4125.32 h60
  text "20-30 um" at 12675.14,4125.32 h60
  text "BOARD FINISH:" at 11333.46,3977.73 h60
  text "SILKSCREEN:" at 11488.68,3867.6 h60
  text "X" at 12446.46,3867.6 h60
  text "TOP" at 12563.46,3867.6 h60
  text "X" at 12956.46,3867.6 h60
  text "BOTTOM" at 13074.46,3867.6 h60
  text "SILKSCREEN COLOR:" at 11488.68,3712.41 h60
  text "X" at 12445.46,3712.41 h60
  text "WHITE" at 12563.46,3712.41 h60
  text "OTHER" at 13074.46,3712.41 h60
  text "X" at 13164.32,3574.6 h60
  text "BLUE" at 13784.43,3573.82 h60
  text "GREEN" at 12694.46,3568.96 h60
  text "OTHER" at 13312.46,3568.96 h60
  text "SOLDER RESIST COLOR:" at 11488.68,3562.1 h60
  text "X" at 13166.9,3417.31 h60
  text "MATTE" at 12694.46,3414.71 h60
  text "SEMI-GLOSS" at 13312,3414.07 h60
  text "IMMERSION GOLD (ENIG)" at 12394.46,3241.94 h60
  text "ENEPIG" at 13732,3234.72 h60
  text "SURFACE FINISH:" at 11333.46,3233.72 h60
  text "X" at 12216.46,3233.72 h60
  text "IMM. TIN/SILVER OR EQUIV" at 11663,3096.4 h60
  text "OTHER" at 13094.46,3092.47 h60
  text "ARRAY/PANEL:" at 11333.46,2937.09 h60
  text "CUT AND TRIM PER M1 BOARD OUTLINE" at 12394.46,2928.87 h60
  text "N.C. ROUTE" at 12394.46,2792.9 h60
  text "X" at 13082.46,2792.9 h60
  text "V. SCORE" at 13260.46,2792.9 h60
  text "CERTIFICATION:" at 11333.46,2663.77 h60
  text "MATERIALS AND WORKMANSHIP FOR ALL PCBS" at 12058.46,2663.77 h60
  text "TO MEET OR EXCEED THE REQUIREMENTS OF:" at 12058.46,2569.71 h60
  text "X" at 11695.97,2441.08 h60
  text "ANSI IPC-A-600F CLASS ->" at 11823.96,2441.08 h60
  text "X" at 13471.97,2441.08 h60
  text "2" at 13581.96,2441.08 h60
  text "1" at 13266.96,2439.58 h60
  text "3" at 13935.96,2439.58 h60
  text "X" at 12507.97,2293.39 h60
  text "RoHS" at 12635.96,2293.39 h60
  text "OTHER" at 13280.36,2293.39 h60
  text "PER ORDER" at 13677.42,2293.39 h60
  text "ALL BOARDS MUST MEET OR EXCEED UL94-V0 REQUIREMENTS." at 11361,2139.57 h60
  text "PCB MUST BEAR THE UL94V-0 UL REGISTERED MATERIAL ID NUMBER" at 11361,2023.5 h60
  text "ADDITIONAL REQUIREMENTS:" at 11333.46,1854.08 h60
  text "MICROSECTION:" at 11408.23,1746.95 h60
  text "YES" at 12313.96,1746.95 h60
  text "REQUIRED" at 13175.46,1602.62 h60
  text "BARE BOARD ELEC. TEST:" at 11408.23,1599.76 h60
  text "NONE" at 12713.96,1599.76 h60
  text "X" at 13057.46,1599.76 h60
  text "PER ORDER" at 13767.46,1599.76 h60
  text "XX MIL VIAS REQUIRE NON-CONDUCTIVE FILL AND PLANARIZE" at 11576.38,1394.82 h59
  text "XX MIL VIAS REQUIRE CONDUCTIVE FILL AND PLANARIZE" at 11584.38,1290.84 h60
  text "OUTER XX MIL TRACES REQUIRE 50 OHM SINGLE-ENDED IMPEDANCE" at 11583.39,1127.46 h58
  text "LAYER 2 & 3 (INNER LAYERS) XX MIL WIDE, XX MIL SPACE / TRACES REQUIRE 100 OHM DIFFERENTIAL IMPEDANCE" at 11575.39,891.74 h60
  text ".Layer_Name" at 577,-858.49 h60
M11 Gerber Information:
  lines w10: -292,-930.17 6308,-930.17 ; -292,-726.83 6310,-726.83 ; -292,-523.5 -292,-1133.5 3713,-1133.5 6310,-1133.5 6310,-523.5 -291.5,-523.5 -291.5,-1133.5 1284,-1133.5 ; 2173,-1133.5 2173,-523.5 ; 3440,-726.83 3440,-523.5 ; 4280,-726.83 4280,-523.5 ; 4902,-1140 4902,-937.17
  text "ALL ARTWORK VIEWED FROM TOP SIDE" at -228.5,-655.67 h60
  text "BOARD #:" at 2248,-655.67 h60
  text ".PRJ_Number" at 2793.5,-655.67 h60
  text "REV:" at 3638,-655.67 h60
  text ".PCB_Rev" at 3929.5,-655.67 h60
  text "SVN REV:" at 4476,-655.67 h60
  text ".VersionControl_RevNumber" at 4982,-655.67 h60
  text "LAYER NAME =" at -228.5,-858.49 h60
  text "TID #:" at 2248,-859 h60
  text ".TID" at 2793.5,-859 h60
  text "PLOT NAME =" at -228.5,-1064.34 h60
  text ".plot_File_Name" at 577,-1064.34 h60
  text "GENERATED    :" at 2250,-1064.34 h60
  text ".Print_Date" at 3119.5,-1064.34 h60
  text ".Print_Time" at 3848.5,-1064.34 h60
  text "TEXAS INSTRUMENTS" at 5113,-1064.34 h60
M12 Stackup:
  drawing of 817 lines, arcs and shapes, not listed
  text "LAYER STACK-UP :" at 5880.75,7882.09 h80
  text "Layer" at 5940.26,7637.8 h60
  text "Name" at 6350.17,7637.8 h60
  text "Material" at 7479.85,7637.8 h60
  text "Thickness" at 8339.62,7637.8 h60
  text "Constant" at 8989.45,7637.8 h60
  text "Board Layer Stack" at 9559.31,7637.8 h60
  text "Top Overlay" at 6350.17,7517.8 h60
  text "Top Solder" at 6350.17,7397.8 h60
  text "Solder Resist" at 7479.85,7397.8 h60
  text "0.80mil" at 8339.62,7397.8 h60
  text "3.5" at 8989.45,7397.8 h60
  text "1" at 5940.26,7277.8 h60
  text "Top Layer" at 6350.17,7277.8 h60
  text "Copper" at 7479.85,7277.8 h60
  text "2.10mil" at 8339.62,7277.8 h60
  text "Dielectric 1" at 6350.17,7157.8 h60
  text "FR-4 High Tg" at 7479.85,7157.8 h60
  text "4.00mil" at 8339.62,7157.8 h60
  text "4.2" at 8989.45,7157.8 h60
  text "2" at 5940.26,7037.8 h60
  text "GND 1" at 6350.17,7037.8 h60
  text "Copper" at 7479.85,7037.8 h60
  text "2.80mil" at 8339.62,7037.8 h60
  text "Dielectric 2" at 6350.17,6917.8 h60
  text "FR-4 High Tg" at 7479.85,6917.8 h60
  text "6.00mil" at 8339.62,6917.8 h60
  text "4.2" at 8989.45,6917.8 h60
  text "3" at 5940.26,6797.8 h60
  text "SIGNAL 1" at 6350.17,6797.8 h60
  text "Copper" at 7479.85,6797.8 h60
  text "1.40mil" at 8339.62,6797.8 h60
  text "Dielectric 3" at 6350.17,6677.8 h60
  text "FR-4 High Tg" at 7479.85,6677.8 h60
  text "6.00mil" at 8339.62,6677.8 h60
  text "4.2" at 8989.45,6677.8 h60
  text "4" at 5940.26,6557.8 h60
  text "GND 2" at 6350.17,6557.8 h60
  text "Copper" at 7479.85,6557.8 h60
  text "1.40mil" at 8339.62,6557.8 h60
  text "Dielectric 4" at 6350.17,6437.8 h60
  text "FR-4 High Tg" at 7479.85,6437.8 h60
  text "6.00mil" at 8339.62,6437.8 h60
  text "4.2" at 8989.45,6437.8 h60
  text "5" at 5940.26,6317.8 h60
  text "SIGNAL 2" at 6350.17,6317.8 h60
  text "Copper" at 7479.85,6317.8 h60
  text "1.40mil" at 8339.62,6317.8 h60
  text "Dielectric 5" at 6350.17,6197.8 h60
  text "FR-4 High Tg" at 7479.85,6197.8 h60
  text "6.00mil" at 8339.62,6197.8 h60
  text "4.2" at 8989.45,6197.8 h60
  text "6" at 5940.26,6077.8 h60
  text "PWR SPLIT PLANE 1" at 6350.17,6077.8 h60
  text "Copper" at 7479.85,6077.8 h60
  text "1.40mil" at 8339.62,6077.8 h60
  text "Dielectric 6" at 6350.17,5957.8 h60
  text "FR-4 High Tg" at 7479.85,5957.8 h60
  text "4.00mil" at 8339.62,5957.8 h60
  text "4.1" at 8989.45,5957.8 h60
  text "7" at 5940.26,5837.8 h60
  text "GND 3" at 6350.17,5837.8 h60
  text "Copper" at 7479.85,5837.8 h60
  text "1.40mil" at 8339.62,5837.8 h60
  text "Dielectric 7" at 6350.17,5717.8 h60
  text "FR-4 High Tg" at 7479.85,5717.8 h60
  text "3.60mil" at 8339.62,5717.8 h60
  text "4.2" at 8989.45,5717.8 h60
  text "8" at 5940.26,5597.8 h60
  text "GND 4" at 6350.17,5597.8 h60
  text "Copper" at 7479.85,5597.8 h60
  text "1.40mil" at 8339.62,5597.8 h60
  text "Dielectric 8" at 6350.17,5477.8 h60
  text "FR-4 High Tg" at 7479.85,5477.8 h60
  text "4.00mil" at 8339.62,5477.8 h60
  text "4.1" at 8989.45,5477.8 h60
  text "9" at 5940.26,5357.8 h60
  text "PWR SPLIT PLANE 2" at 6350.17,5357.8 h60
  text "Copper" at 7479.85,5357.8 h60
  text "1.40mil" at 8339.62,5357.8 h60
  text "Dielectric 9" at 6350.17,5237.8 h60
  text "FR-4 High Tg" at 7479.85,5237.8 h60
  text "6.00mil" at 8339.62,5237.8 h60
  text "4.2" at 8989.45,5237.8 h60
  text "10" at 5940.26,5117.8 h60
  text "SIGNAL 3" at 6350.17,5117.8 h60
  text "Copper" at 7479.85,5117.8 h60
  text "1.40mil" at 8339.62,5117.8 h60
  text "Dielectric 10" at 6350.17,4997.8 h60
  text "FR-4 High Tg" at 7479.85,4997.8 h60
  text "6.00mil" at 8339.62,4997.8 h60
  text "4.2" at 8989.45,4997.8 h60
  text "11" at 5940.26,4877.8 h60
  text "GND 5" at 6350.17,4877.8 h60
  text "Copper" at 7479.85,4877.8 h60
  text "1.40mil" at 8339.62,4877.8 h60
  text "Dielectric 11" at 6350.17,4757.8 h60
  text "FR-4 High Tg" at 7479.85,4757.8 h60
  text "6.00mil" at 8339.62,4757.8 h60
  text "4.2" at 8989.45,4757.8 h60
  text "12" at 5940.26,4637.8 h60
  text "SIGNAL 4" at 6350.17,4637.8 h60
  text "Copper" at 7479.85,4637.8 h60
  text "1.40mil" at 8339.62,4637.8 h60
  text "Dielectric 12" at 6350.17,4517.8 h60
  text "FR-4 High Tg" at 7479.85,4517.8 h60
  text "6.00mil" at 8339.62,4517.8 h60
  text "4.2" at 8989.45,4517.8 h60
  text "13" at 5940.26,4397.8 h60
  text "GND 6" at 6350.17,4397.8 h60
  text "Copper" at 7479.85,4397.8 h60
  text "2.80mil" at 8339.62,4397.8 h60
  text "Dielectric 13" at 6350.17,4277.8 h60
  text "FR-4 High Tg" at 7479.85,4277.8 h60
  text "4.00mil" at 8339.62,4277.8 h60
  text "4.2" at 8989.45,4277.8 h60
  text "14" at 5940.26,4157.8 h60
  text "Bottom Layer" at 6350.17,4157.8 h60
  text "Copper" at 7479.85,4157.8 h60
  text "2.10mil" at 8339.62,4157.8 h60
  text "Bottom Solder" at 6350.17,4037.8 h60
  text "Solder Resist" at 7479.85,4037.8 h60
  text "0.80mil" at 8339.62,4037.8 h60
  text "3.5" at 8989.45,4037.8 h60
  text "Bottom Overlay" at 6350.17,3917.8 h60
  text "THIS IS AN IMPEDANCE CONTROLLED BOARD." at 6737.16,3614.45 h80
  text "NOTE :" at 5638.6,3525.98 h80
  text "1. ALL CORE AND PREPREG THICKNESSES ARE UP TO FAB SHOP TO SELECT." at 5649.08,3310.89 h80
  text "2. EXTERNAL LAYER CU THICKNESSES ARE FINISHED THICKNESS AFTER PLATING." at 5649.08,3104.53 h80
  text ".Layer_Name" at 577,-858.49 h60
M13 Component Bodies Top:
  text ".Layer_Name" at 577,-858.49 h60
M14 Component Bodies Bottom:
  text ".Layer_Name" at 577,-858.49 h60
M15 Courtyards Top:
  text ".Layer_Name" at 577,-858.49 h60
M16 Courtyards Bottom:
  text ".Layer_Name" at 577,-858.49 h60
Drill Drawing:
  lines w10: 459.78,5529.66 519.65,5529.66 519.65,5589.53 459.78,5589.53 459.78,5529.66
  lines w12: 405.76,5085.12 5248.07,5085.12 ; 405.76,6701.63 5248.07,6701.63 ; 434.57,6905.13 1334.57,6905.13 ; 434.57,6939.11 1334.57,6939.11 ; 771.79,4950.41 771.79,6836.34 ; 1131.53,4950.41 1131.53,6836.34 ; 1820.95,4950.41 1820.95,6836.34 ; 2101.65,4950.41 2101.65,6836.34 ; 2508.06,4950.41 2508.06,6836.34 ; 3292.02,4950.41 3292.02,6836.34 ; 3900.38,4950.41 3900.38,6836.34 ; 4634.45,4950.41 4634.45,6836.34 ; 405.76,4950.41 5248.07,4950.41 5248.07,6836.34 405.76,6836.34 405.76,4950.41
  text "DRILL TABLE:" at 443.57,6988.54 h80
  text "Symbol" at 486.59,6742.04 h78
  text "Quantity" at 812.2,6742.04 h78
  text "Finished Hole Size" at 1171.94,6742.04 h78
  text "Plated" at 1861.36,6742.04 h78
  text "Hole Type" at 2142.06,6742.04 h78
  text "Drill Layer Pair" at 2548.47,6742.04 h78
  text "Hole Length" at 3332.44,6742.04 h78
  text "Routed Path Length" at 3940.79,6742.04 h78
  text "Hole Tolerance" at 4674.87,6742.04 h78
  text "170" at 812.2,6607.33 h65
  text "7.87mil (0.200mm)" at 1171.94,6607.33 h65
  text "PTH" at 1861.36,6607.33 h65
  text "Round" at 2142.06,6607.33 h65
  text "Top Layer - Bottom Layer" at 2548.47,6607.33 h65
  text "-" at 3332.44,6607.33 h65
  text "-" at 3940.79,6607.33 h65
  text "A" at 459.76,6597.34 h59.87
  text "363" at 812.2,6472.62 h65
  text "8.00mil (0.203mm)" at 1171.94,6472.62 h65
  text "PTH" at 1861.36,6472.62 h65
  text "Round" at 2142.06,6472.62 h65
  text "Top Layer - Bottom Layer" at 2548.47,6472.62 h65
  text "-" at 3332.44,6472.62 h65
  text "-" at 3940.79,6472.62 h65
  text "B" at 459.76,6462.63 h59.87
  text "716" at 812.2,6337.91 h65
  text "10.00mil (0.254mm)" at 1171.94,6337.91 h65
  text "PTH" at 1861.36,6337.91 h65
  text "Round" at 2142.06,6337.91 h65
  text "Top Layer - Bottom Layer" at 2548.47,6337.91 h65
  text "-" at 3332.44,6337.91 h65
  text "-" at 3940.79,6337.91 h65
  text "E" at 459.76,6327.92 h59.87
  text "24" at 812.2,6203.21 h65
  text "19.69mil (0.500mm)" at 1171.94,6203.21 h65
  text "PTH" at 1861.36,6203.21 h65
  text "Round" at 2142.06,6203.21 h65
  text "Top Layer - Bottom Layer" at 2548.47,6203.21 h65
  text "-" at 3332.44,6203.21 h65
  text "-" at 3940.79,6203.21 h65
  text "F" at 459.76,6193.22 h59.87
  text "15" at 812.2,6068.5 h65
  text "37.99mil (0.965mm)" at 1171.94,6068.5 h65
  text "PTH" at 1861.36,6068.5 h65
  text "Round" at 2142.06,6068.5 h65
  text "Top Layer - Bottom Layer" at 2548.47,6068.5 h65
  text "-" at 3332.44,6068.5 h65
  text "-" at 3940.79,6068.5 h65
  text "G" at 459.76,6058.51 h59.87
  text "20" at 812.2,5933.79 h65
  text "44.88mil (1.140mm)" at 1171.94,5933.79 h65
  text "PTH" at 1861.36,5933.79 h65
  text "Round" at 2142.06,5933.79 h65
  text "Top Layer - Bottom Layer" at 2548.47,5933.79 h65
  text "-" at 3332.44,5933.79 h65
  text "-" at 3940.79,5933.79 h65
  text "H" at 459.76,5923.8 h59.87
  text "18" at 812.2,5799.08 h65
  text "45.28mil (1.150mm)" at 1171.94,5799.08 h65
  text "PTH" at 1861.36,5799.08 h65
  text "Round" at 2142.06,5799.08 h65
  text "Top Layer - Bottom Layer" at 2548.47,5799.08 h65
  text "-" at 3332.44,5799.08 h65
  text "-" at 3940.79,5799.08 h65
  text "I" at 469.74,5789.09 h59.87
  text "2" at 812.2,5664.37 h65
  text "55.12mil (1.400mm)" at 1171.94,5664.37 h65
  text "NPTH" at 1861.36,5664.37 h65
  text "Round" at 2142.06,5664.37 h65
  text "Top Layer - Bottom Layer" at 2548.47,5664.37 h65
  text "-" at 3332.44,5664.37 h65
  text "-" at 3940.79,5664.37 h65
  text "J" at 459.76,5654.38 h59.87
  text "1" at 812.2,5529.66 h65
  text "63.00mil (1.600mm)" at 1171.94,5529.66 h65
  text "PTH" at 1861.36,5529.66 h65
  text "Round" at 2142.06,5529.66 h65
  text "Top Layer - Bottom Layer" at 2548.47,5529.66 h65
  text "-" at 3332.44,5529.66 h65
  text "-" at 3940.79,5529.66 h65
  text "2" at 812.2,5394.95 h65
  text "66.93mil (1.700mm)" at 1171.94,5394.95 h65
  text "PTH" at 1861.36,5394.95 h65
  text "Slot" at 2142.06,5394.95 h65
  text "Top Layer - Bottom Layer" at 2548.47,5394.95 h65
  text "35.43mil (0.900mm)" at 3332.44,5394.95 h65
  text "-31.50mil (-0.800mm)" at 3940.79,5394.95 h65
  text "K" at 459.76,5384.96 h59.87
  text "2" at 812.2,5260.24 h65
  text "106.30mil (2.700mm)" at 1171.94,5260.24 h65
  text "PTH" at 1861.36,5260.24 h65
  text "Slot" at 2142.06,5260.24 h65
  text "Top Layer - Bottom Layer" at 2548.47,5260.24 h65
  text "35.43mil (0.900mm)" at 3332.44,5260.24 h65
  text "-70.87mil (-1.800mm)" at 3940.79,5260.24 h65
  text "L" at 459.76,5250.25 h59.87
  text "4" at 812.2,5125.53 h65
  text "157.00mil (3.988mm)" at 1171.94,5125.53 h65
  text "PTH" at 1861.36,5125.53 h65
  text "Round" at 2142.06,5125.53 h65
  text "Top Layer - Bottom Layer" at 2548.47,5125.53 h65
  text "-" at 3332.44,5125.53 h65
  text "-" at 3940.79,5125.53 h65
  text "M" at 459.76,5115.54 h59.87
  text "1337 Total" at 812.2,4990.82 h65
  text "Slot definitions :" at 486.59,4896.53 h65
  text "Routed Path Length" at 974.19,4896.53 h65
  text "= Calculated from tool start centre position to tool end centre position." at 1558.31,4896.53 h65
  text "Hole Length" at 974.19,4842.64 h65
  text "= Routed Path Length + Tool Size = Slot length as defined in the PCB layout" at 1342.07,4842.64 h65
  text ".Layer_Name" at 577,-858.49 h60
M17 Embedded Cavity:
  text ".Layer_Name" at 577,-858.49 h60
M18 Embedded Assembly:
  text ".Layer_Name" at 577,-858.49 h60
M19 Embedded Keepout:
  text ".Layer_Name" at 577,-858.49 h60

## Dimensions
4622.05,2417.32 to 1951.09,2429.52 on M2 Board Dimensions
4953.53,-32.07 to 5953.53,-32.07 on M2 Board Dimensions
0,0 to 0,2598.43 on M2 Board Dimensions
0,0 to 4803.15,0 on M2 Board Dimensions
